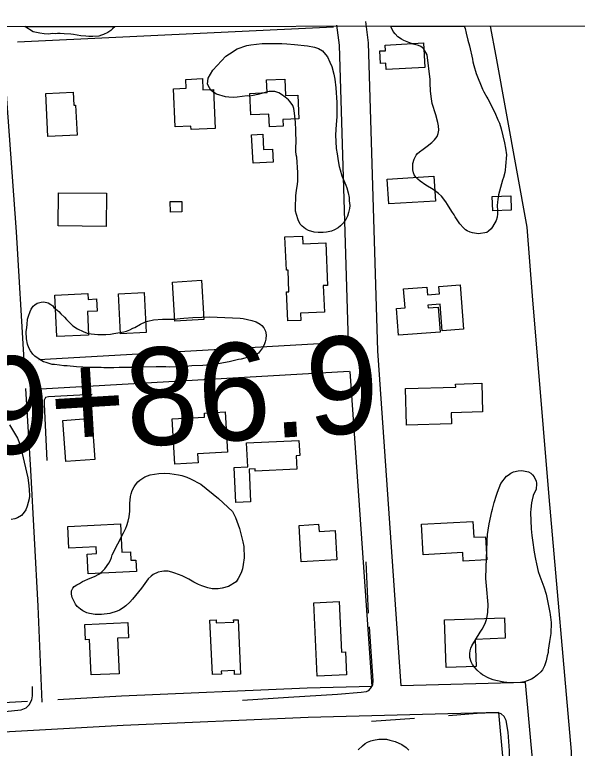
# Model space of a CAD drawing. Extents: x 3297716 to 3335574, y 688621 to 713991.
# Drawn here: x 3321388 to 3321965, y 711464 to 712216 of the extents above; entities that cross this region are included whole.
import ezdxf

# ---------------------------------------------------------------- set-up
doc = ezdxf.new("R2010")
doc.units = 0
for name, color, linetype in [('V-BLDG-OTLN', 7, 'Continuous'), ('V-GRID-FRAM', 7, 'Continuous'), ('V-LEVE-TOET', 7, 'Continuous'), ('V-ROAD-CNTR', 7, 'Continuous'), ('V-SITE-VEGE', 7, 'Continuous'), ('V-SURV-IDEN', 7, 'Continuous'), ('V-TOPO-SHOR', 7, 'Continuous')]:
    doc.layers.add(name, color=color, linetype=linetype)

msp = doc.modelspace()

# ---------------------------------------------------------------- linework, layer by layer
at = {"layer": 'V-BLDG-OTLN'}
for points in [[(3321808.59, 712162.12), (3321769.11, 712160.01), (3321768.77, 712166.46), (3321763.14, 712166.16), (3321762.45, 712179.03), (3321768.41, 712179.35), (3321768.1, 712185.17), (3321807.25, 712187.27)], [(3321552.47, 712101.35), (3321550.87, 712140.29), (3321563.62, 712140.82), (3321563.24, 712149.96), (3321580.44, 712150.67), (3321580.91, 712139.11), (3321591.73, 712139.56), (3321593.39, 712099.41), (3321568.7, 712098.39), (3321568.55, 712102.02)], [(3321648.59, 712114.35), (3321630.17, 712113.51), (3321629.16, 712135.51), (3321646.8, 712136.32), (3321646.21, 712149.28), (3321665.05, 712150.14), (3321665.82, 712133.21), (3321678.23, 712133.79), (3321679.34, 712109.47), (3321663.06, 712108.72), (3321663.37, 712101.92), (3321649.19, 712101.27)], [(3321451.8, 712092.74), (3321421.81, 712091.3), (3321419.7, 712135.32), (3321447.71, 712136.66), (3321448.34, 712123.48), (3321450.33, 712123.58)], [(3321632.42, 712064.04), (3321630.93, 712092.99), (3321642.33, 712093.57), (3321643.13, 712077.82), (3321652.24, 712078.28), (3321652.92, 712065.09)], [(3321819.45, 712025.12), (3321771.54, 712022.29), (3321770.03, 712047.7), (3321817.95, 712050.53)], [(3321482.01, 712033.23), (3321481.71, 711999.1), (3321432.48, 711999.54), (3321432.78, 712033.67)], [(3321896.88, 712030.45), (3321897.34, 712015.73), (3321878.35, 712015.12), (3321877.89, 712029.85)], [(3321547.39, 712024.49), (3321559.13, 712024.68), (3321559.3, 712013.95), (3321547.56, 712013.76)], [(3321706.92, 711982.3), (3321708.86, 711938.62), (3321704.46, 711938.43), (3321705.68, 711911.05), (3321680.97, 711909.95), (3321681.29, 711902.61), (3321668.14, 711902.03), (3321666.81, 711931.86), (3321669.23, 711931.97), (3321668.24, 711954.26), (3321666.52, 711954.18), (3321665, 711988.37), (3321683.1, 711989.17), (3321683.46, 711981.25)], [(3321579.32, 711943.76), (3321581.94, 711903.73), (3321552.19, 711901.79), (3321549.58, 711941.81)], [(3321844.93, 711939.01), (3321848.38, 711893.7), (3321826.45, 711892.03), (3321824.37, 711919.36), (3321811.77, 711918.4), (3321811.98, 711915.57), (3321822.3, 711916.36), (3321824.26, 711890.68), (3321781.51, 711887.42), (3321779.42, 711914.8), (3321788.32, 711915.48), (3321786.82, 711935.09), (3321810.61, 711936.9), (3321811.23, 711928.89), (3321823.62, 711929.83), (3321823.04, 711937.34)], [(3321431.01, 711886.08), (3321429.02, 711928.7), (3321462.88, 711930.28), (3321463.16, 711924.21), (3321471.73, 711924.61), (3321472.31, 711912.19), (3321462.35, 711911.73), (3321463.47, 711887.59)], [(3321496.25, 711888.74), (3321494.2, 711929.8), (3321520.79, 711931.12), (3321522.84, 711890.07)], [(3321836.13, 711796.48), (3321789.85, 711795.16), (3321788.78, 711832.67), (3321840.32, 711834.14), (3321840.23, 711837.38), (3321866.99, 711838.14), (3321867.83, 711808.84), (3321835.8, 711807.93)], [(3321549.52, 711801.54), (3321582.69, 711803.37), (3321582.46, 711807.52), (3321603.92, 711808.71), (3321606.2, 711767.52), (3321575.37, 711765.81), (3321575.89, 711756.52), (3321552.09, 711755.21)], [(3321467.08, 711802.18), (3321470.14, 711760.03), (3321440.14, 711757.86), (3321437.08, 711800)], [(3321625.77, 711776.98), (3321679.45, 711779.58), (3321680.21, 711763.91), (3321676.64, 711763.74), (3321677.31, 711750.08), (3321634.67, 711748.02), (3321634.55, 711750.49), (3321628.28, 711750.19), (3321629.91, 711716.46), (3321614.76, 711715.72), (3321613, 711751.88), (3321626.95, 711752.56)], [(3321442.2, 711691.28), (3321496.41, 711693.86), (3321497.79, 711664.86), (3321506.53, 711665.27), (3321506.95, 711656.57), (3321512.06, 711656.82), (3321512.62, 711645.1), (3321463.18, 711642.74), (3321462.22, 711662.9), (3321471.74, 711663.36), (3321471.41, 711670.35), (3321443.25, 711669.01)], [(3321681.87, 711654.99), (3321679.67, 711692.37), (3321699.64, 711693.55), (3321700.07, 711686.17), (3321716.71, 711687.15), (3321718.48, 711657.14)], [(3321805.26, 711693.49), (3321857.9, 711696.34), (3321858.78, 711680.12), (3321870.92, 711680.77), (3321872.21, 711657.08), (3321848.03, 711655.77), (3321847.56, 711664.46), (3321806.95, 711662.27)], [(3321698.23, 711537.73), (3321694.91, 711612.98), (3321720.86, 711614.12), (3321723.14, 711562.42), (3321727.29, 711562.6), (3321728.33, 711539.06)], [(3321459.75, 711590.78), (3321503.95, 711592.7), (3321504.64, 711577.03), (3321493.36, 711576.53), (3321494.94, 711540.22), (3321466.15, 711538.96), (3321464.58, 711575.24), (3321460.44, 711575.06)], [(3321617, 711595.58), (3321619.52, 711539.8), (3321613.34, 711539.52), (3321613.16, 711543.5), (3321599.71, 711542.89), (3321599.85, 711539.78), (3321590.66, 711539.36), (3321588.14, 711595.23), (3321594.36, 711595.51), (3321594.51, 711592.24), (3321612.53, 711593.06), (3321612.42, 711595.37)], [(3321830.42, 711546.46), (3321828.68, 711595.38), (3321890.33, 711597.57), (3321891.07, 711576.51), (3321860.4, 711575.42), (3321861.39, 711547.57)]]:
    msp.add_lwpolyline(points, close=True, dxfattribs=at)
at = {"layer": 'V-GRID-FRAM'}
msp.add_lwpolyline([(3301838.48, 712184.22), (3333346.19, 712216.3), (3333372.64, 694031.53), (3301849.06, 693999.43), (3301838.48, 712184.22)], dxfattribs=at)
at = {"layer": 'V-LEVE-TOET'}
msp.add_lwpolyline([(3322018.75, 710120.99), (3322017.11, 710139.56), (3322019.86, 710157.32), (3322023.4, 710174.89), (3322027.98, 710190.84), (3322033.99, 710207.05), (3322036.58, 710224.66), (3322036.04, 710236.16), (3322023.44, 710391.28), (3322010.09, 710623.54), (3321976.79, 711142.09), (3321968.23, 711184.67), (3321964.85, 711202.52), (3321959.29, 711460.32), (3321936.14, 711721.54), (3321919.03, 711928), (3321913.61, 711998.4), (3321881.83, 712173.64), (3321876.05, 712204.62)], dxfattribs=at)
at = {"layer": 'V-ROAD-CNTR'}
for points in [[(3321714.87, 712203.36), (3321390.53, 712188.22)], [(3321730.18, 711880.31), (3321721.01, 712185.06), (3321718.49, 712205.51)], [(3321784.5, 711527.85), (3321760.46, 711871.56), (3321750.96, 712187.35), (3321748.27, 712209.18)], [(3321397.37, 711861.61), (3321389.72, 711993.51), (3321376.57, 712172.22), (3321375.71, 712187.52)], [(3321472.96, 712192.08), (3321472.96, 712192.08)], [(3321730.18, 711880.31), (3321412.51, 711862.2)], [(3321731.08, 711850.31), (3321414.47, 711832.26)], [(3321754.48, 711527.07), (3321731.87, 711850.36)], [(3321415.94, 711510.97), (3321411.82, 711609.63), (3321404.29, 711748.96), (3321399.08, 711832.74)], [(3321754.48, 711527.07), (3321687.98, 711525.33), (3321497.45, 711517.16), (3321431.86, 711513.47)], [(3322005.03, 710252.58), (3321988.8, 710448.52), (3321987.02, 710552.46), (3321967.93, 710803.96), (3321961.25, 710892.18), (3321944.29, 711176.62), (3321912.08, 711531.19), (3321784.5, 711527.85)], [(3321401.02, 711511.73), (3321245.66, 711502.99), (3321148.07, 711496.71), (3321098.11, 711495.85), (3320964.97, 711492.11), (3320679.58, 711472.85), (3320665.92, 711471.69)], [(3321909.86, 711224.02), (3321884.74, 711500.46), (3321689.02, 711495.35), (3321498.93, 711487.2), (3321247.47, 711473.04), (3321149.29, 711466.72), (3321098.79, 711465.86), (3320966.4, 711462.13), (3320681.86, 711442.94), (3320668.08, 711441.77)]]:
    msp.add_lwpolyline(points, dxfattribs=at)
at = {"layer": 'V-SITE-VEGE'}
for p, q in [((3321398.01, 712204.13), (3321490.93, 712204.23)), ((3321406.88, 712198.83), (3321398.01, 712204.13)), ((3321490.64, 712203.88), (3321488.17, 712201.6)), ((3321490.93, 712204.23), (3321490.64, 712203.88)), ((3321774.09, 712204.52), (3321849.16, 712204.59)), ((3321774.27, 712203.49), (3321774.09, 712204.52)), ((3321776.24, 712198.96), (3321774.27, 712203.49)), ((3321849.16, 712204.59), (3321850.03, 712202.22)), ((3321413.57, 712197.38), (3321406.88, 712198.83)), ((3321418.11, 712196.61), (3321413.57, 712197.38)), ((3321422.07, 712196.45), (3321418.11, 712196.61)), ((3321424.66, 712196.55), (3321422.07, 712196.45)), ((3321426.65, 712196.86), (3321424.66, 712196.55)), ((3321429.63, 712196.75), (3321426.65, 712196.86)), ((3321431.82, 712197.06), (3321429.63, 712196.75)), ((3321434.4, 712196.96), (3321431.82, 712197.06)), ((3321438.36, 712196.8), (3321434.4, 712196.96)), ((3321445.28, 712196.14), (3321438.36, 712196.8)), ((3321448.05, 712195.83), (3321445.28, 712196.14)), ((3321455.74, 712194.53), (3321448.05, 712195.83)), ((3321476.8, 712195.3), (3321474.19, 712194.41)), ((3321478.81, 712195.82), (3321476.8, 712195.3)), ((3321483.26, 712198.02), (3321478.81, 712195.82)), ((3321486.32, 712200.08), (3321483.26, 712198.02)), ((3321488.17, 712201.6), (3321486.32, 712200.08)), ((3321778.15, 712196.58), (3321776.24, 712198.96)), ((3321781.11, 712193.54), (3321778.15, 712196.58)), ((3321850.03, 712202.22), (3321851.23, 712197.4)), ((3321851.23, 712197.4), (3321852.64, 712190.12)), ((3321460.88, 712194.14), (3321455.74, 712194.53)), ((3321463.85, 712194.02), (3321460.88, 712194.14)), ((3321467.83, 712194.06), (3321463.85, 712194.02)), ((3321474.19, 712194.41), (3321467.83, 712194.06)), ((3321784.71, 712191.25), (3321781.11, 712193.54)), ((3321787.27, 712189.91), (3321784.71, 712191.25)), ((3321792.11, 712187.72), (3321787.27, 712189.91)), ((3321796.66, 712186.16), (3321792.11, 712187.72)), ((3321852.64, 712190.12), (3321854.4, 712184.21)), ((3321801.98, 712184.72), (3321796.66, 712186.16)), ((3321804.56, 712183.7), (3321801.98, 712184.72)), ((3321807.25, 712181.75), (3321804.56, 712183.7)), ((3321811.14, 712174.98), (3321807.25, 712181.75)), ((3321854.4, 712184.21), (3321857.71, 712170.54)), ((3321814.14, 712149.64), (3321811.14, 712174.98)), ((3321857.71, 712170.54), (3321858.07, 712167.92)), ((3321858.07, 712167.92), (3321859, 712164.19)), ((3321859, 712164.19), (3321861.29, 712155.95)), ((3321814.16, 712146.26), (3321814.14, 712149.64)), ((3321861.29, 712155.95), (3321867.74, 712140.01)), ((3321814.6, 712137.79), (3321814.16, 712146.26)), ((3321815.37, 712130.07), (3321814.6, 712137.79)), ((3321867.74, 712140.01), (3321869.17, 712137.18)), ((3321869.17, 712137.18), (3321872.34, 712131.68)), ((3321816.25, 712125.11), (3321815.37, 712130.07)), ((3321872.34, 712131.68), (3321873.18, 712129.8)), ((3321873.18, 712129.8), (3321880.48, 712115.98)), ((3321819.79, 712113.44), (3321816.25, 712125.11)), ((3321821.95, 712105.66), (3321819.79, 712113.44)), ((3321880.48, 712115.98), (3321883.57, 712108.32)), ((3321822.73, 712102.1), (3321821.95, 712105.66)), ((3321883.57, 712108.32), (3321885.13, 712104.88)), ((3321885.13, 712104.88), (3321886.9, 712099.12)), ((3321822.42, 712094.27), (3321822.88, 712097.79)), ((3321822.88, 712097.79), (3321822.73, 712102.1)), ((3321886.9, 712099.12), (3321890.33, 712084.68)), ((3321818.48, 712087.81), (3321821.24, 712091.39)), ((3321821.24, 712091.39), (3321822.42, 712094.27)), ((3321811.16, 712081.48), (3321815.77, 712085.3)), ((3321815.77, 712085.3), (3321818.48, 712087.81)), ((3321890.33, 712084.68), (3321891.35, 712079.41)), ((3321801.17, 712073.88), (3321803.09, 712075.65)), ((3321803.09, 712075.65), (3321806.88, 712078.27)), ((3321806.88, 712078.27), (3321811.16, 712081.48)), ((3321891.35, 712079.41), (3321892.47, 712072.45)), ((3321796.31, 712063.61), (3321797.56, 712068.02)), ((3321797.56, 712068.02), (3321799.73, 712072.24)), ((3321799.73, 712072.24), (3321801.17, 712073.88)), ((3321892.47, 712072.45), (3321891.55, 712060.8)), ((3321796.2, 712060.69), (3321796.31, 712063.61)), ((3321796.21, 712057), (3321796.2, 712060.69)), ((3321891.55, 712060.8), (3321891.08, 712056.67)), ((3321797.01, 712053.89), (3321796.21, 712057)), ((3321797.86, 712052.02), (3321797.01, 712053.89)), ((3321799.9, 712049.17), (3321797.86, 712052.02)), ((3321890.69, 712054.53), (3321889.25, 712049.36)), ((3321891.08, 712056.67), (3321890.69, 712054.53)), ((3321801.37, 712047.57), (3321799.9, 712049.17)), ((3321803.74, 712045.33), (3321801.37, 712047.57)), ((3321809.74, 712041.4), (3321803.74, 712045.33)), ((3321888.22, 712046.47), (3321884.25, 712031.41)), ((3321889.25, 712049.36), (3321888.22, 712046.47)), ((3321817.26, 712036.95), (3321809.74, 712041.4)), ((3321822.79, 712032.74), (3321817.26, 712036.95)), ((3321825.6, 712030.02), (3321822.79, 712032.74)), ((3321830.15, 712024.45), (3321825.6, 712030.02)), ((3321884.25, 712031.41), (3321883.44, 712026.52)), ((3321832.03, 712021.61), (3321830.15, 712024.45)), ((3321836.37, 712014.52), (3321832.03, 712021.61)), ((3321883.19, 712024.07), (3321883.05, 712020.69)), ((3321883.44, 712026.52), (3321883.19, 712024.07)), ((3321838.69, 712011.05), (3321836.37, 712014.52)), ((3321883.05, 712020.69), (3321883.14, 712014.99)), ((3321883.14, 712014.99), (3321883.33, 712012.06)), ((3321839.84, 712008.85), (3321838.69, 712011.05)), ((3321843.32, 712003.64), (3321839.84, 712008.85)), ((3321882.89, 712008.54), (3321881.83, 712005.05)), ((3321883.33, 712012.06), (3321882.89, 712008.54)), ((3321844.48, 712001.75), (3321843.32, 712003.64)), ((3321848.16, 711997.6), (3321844.48, 712001.75)), ((3321881.83, 712005.05), (3321878.19, 711998.58)), ((3321850.54, 711995.51), (3321848.16, 711997.6)), ((3321852.19, 711994.37), (3321850.54, 711995.51)), ((3321855.06, 711993.18), (3321852.19, 711994.37)), ((3321857.49, 711992.32), (3321855.06, 711993.18)), ((3321863.75, 711991.3), (3321857.49, 711992.32)), ((3321872.12, 711992.97), (3321863.75, 711991.3)), ((3321874.02, 711994.28), (3321872.12, 711992.97)), ((3321876.57, 711996.49), (3321874.02, 711994.28)), ((3321878.19, 711998.58), (3321876.57, 711996.49))]:
    msp.add_line(p, q, dxfattribs=at)
for points in [[(3321677.31, 712069.94), (3321676.62, 712072.55), (3321676.16, 712076.14), (3321676.69, 712089.61), (3321676.42, 712092.8), (3321676.42, 712097.96), (3321675.94, 712105.92), (3321674.92, 712115.09), (3321674.12, 712120.08), (3321673.04, 712123.1), (3321670.61, 712126.77), (3321668.7, 712128.82), (3321665.25, 712131.74), (3321661.58, 712134.46), (3321658.86, 712135.96), (3321654.55, 712137.32), (3321649, 712137.54), (3321646, 712136.86), (3321637.37, 712134.42), (3321632.56, 712133.22), (3321628.57, 712132.78), (3321626.2, 712133.07), (3321616.02, 712131.69), (3321612.64, 712131.42), (3321607.48, 712131.62), (3321603.93, 712131.96), (3321594.71, 712134.9), (3321591.03, 712137.23), (3321589.11, 712138.89), (3321587.62, 712141.33), (3321585.78, 712144.98), (3321586.22, 712151.11), (3321591.1, 712159.26), (3321604.57, 712173.61), (3321608.04, 712176.06), (3321616.18, 712181.3), (3321626.04, 712184.68), (3321630.24, 712185.51), (3321641.79, 712186.64), (3321648.94, 712186.76), (3321661.84, 712186.65), (3321667.19, 712186.44), (3321674.91, 712185.74), (3321688.15, 712184.23), (3321695.44, 712182.95), (3321699.55, 712181.6), (3321703.62, 712179.06), (3321706.85, 712175.36), (3321708.74, 712172.91), (3321711.31, 712167.64), (3321713.11, 712163.01), (3321715.2, 712155.39), (3321716.18, 712149.99), (3321717.43, 712141.4), (3321718.41, 712126.08), (3321718.45, 712116.95), (3321718.24, 712111.6), (3321717.54, 712103.69), (3321717.12, 712092.99), (3321717.76, 712079.07), (3321718.74, 712073.67), (3321719.65, 712066.49), (3321720.8, 712060.49), (3321721.67, 712057.28), (3321723.61, 712051.06), (3321727.6, 712041.37), (3321728.49, 712038.76), (3321730.07, 712033.53), (3321731.07, 712028.73), (3321731.14, 712025.35), (3321731.54, 712020.38), (3321731.22, 712017.41), (3321730.27, 712013.48), (3321729.14, 712009.75), (3321726.76, 712004.88), (3321724.25, 712001.61), (3321722.19, 711999.51), (3321719.73, 711997.62), (3321715.87, 711995.39), (3321712.85, 711994.32), (3321707.84, 711993.12), (3321704.45, 711992.66), (3321699.29, 711992.66), (3321694.94, 711993.23), (3321689.26, 711995.04), (3321686.14, 711996.55), (3321682.68, 711999.27), (3321680.77, 712001.33), (3321678.57, 712005.78), (3321676.79, 712011.21), (3321675.94, 712014.62), (3321675.87, 712017.99), (3321676.36, 712030.48), (3321676.98, 712036.21), (3321677.81, 712042.13), (3321678.15, 712045.69), (3321678.49, 712054.41)], [(3321546.74, 711854.82), (3321542.78, 711854.97), (3321533.05, 711854.96), (3321518.16, 711854.75), (3321507.62, 711854.37), (3321494.92, 711854.27), (3321489.55, 711854.08), (3321479.23, 711854.09), (3321476.65, 711854.19), (3321464.55, 711854.27), (3321457.82, 711854.73), (3321451.08, 711854.99), (3321441.6, 711855.96), (3321438.03, 711856.1), (3321433.68, 711856.67), (3321428.75, 711857.46), (3321426.38, 711857.55), (3321419.9, 711859.39), (3321417.35, 711860.29), (3321413.86, 711862.21), (3321408.45, 711865.99), (3321406.34, 711867.86), (3321403.9, 711871.53), (3321402.42, 711874.37), (3321400.8, 711878.4), (3321400.01, 711883.59), (3321399.69, 711890.75), (3321400.07, 711895.3), (3321400.59, 711898.45), (3321401, 711903.8), (3321401.91, 711906.94), (3321403.49, 711911.64), (3321404.58, 711914.18), (3321406.69, 711917.27), (3321408.33, 711918.59), (3321410.97, 711920.28), (3321414.78, 711921.32), (3321417.77, 711921.6), (3321422.1, 711920.64), (3321425.01, 711918.93), (3321426.74, 711917.48), (3321428.06, 711915.84), (3321433.07, 711911.87), (3321435.16, 711909.41), (3321438.79, 711905.89), (3321441.07, 711903.42), (3321447.57, 711897.01), (3321452.21, 711893.85), (3321457.87, 711891.25), (3321462.17, 711889.69), (3321466.3, 711888.73), (3321473.02, 711888.07), (3321481.16, 711888.15), (3321486.14, 711888.55), (3321489.54, 711889.21), (3321495.73, 711890.16), (3321499.93, 711890.99), (3321502.34, 711891.69), (3321505.97, 711893.13), (3321509, 711894.6), (3321511.02, 711895.32), (3321516.71, 711898.67), (3321521.97, 711901.24), (3321524.38, 711901.94), (3321530.18, 711903.3), (3321539.34, 711903.93), (3321541.92, 711903.83), (3321551.45, 711904.05), (3321557.63, 711904.6), (3321561.42, 711905.05), (3321570.57, 711905.69), (3321579.72, 711906.12), (3321587.66, 711906.2), (3321619.17, 711904.97), (3321622.13, 711904.65), (3321631.19, 711902.71), (3321635.49, 711901.15), (3321639.77, 711898.8), (3321641.51, 711897.54), (3321643.39, 711895.09), (3321645.04, 711891.65), (3321645.89, 711887.84), (3321645.52, 711883.49), (3321644.81, 711880.54), (3321643.69, 711877.41), (3321642.19, 711874.49), (3321638, 711868.9), (3321634.75, 711867.05), (3321630.12, 711865.44), (3321620.1, 711862.85), (3321617.3, 711862.37), (3321607.69, 711860.17), (3321601.89, 711859.2), (3321598.48, 711858.34), (3321596.29, 711858.23), (3321588.31, 711856.96), (3321580.94, 711856.25), (3321569.61, 711855.9), (3321566.62, 711855.62)], [(3321499.33, 711684.74), (3321501.78, 711689.5), (3321502.86, 711692.37), (3321504.32, 711696.52), (3321505.31, 711701.17), (3321505.86, 711706.97), (3321505.98, 711710.04), (3321506, 711714.73), (3321506.77, 711721.98), (3321507.36, 711724.55), (3321508.47, 711728.22), (3321510.23, 711731.88), (3321511.61, 711734.09), (3321514.15, 711736.9), (3321516.16, 711738.6), (3321519.32, 711740.9), (3321521.48, 711742.28), (3321523.95, 711743.31), (3321526.9, 711744.33), (3321535.68, 711745.44), (3321541.36, 711745.86), (3321546.85, 711745.65), (3321555.85, 711744.16), (3321559.21, 711743.38), (3321564.49, 711741.72), (3321568.3, 711739.95), (3321578.61, 711734.7), (3321596.8, 711720.07), (3321611.16, 711706.73), (3321614.47, 711700.29), (3321618.41, 711689.3), (3321621.91, 711675.41), (3321622.85, 711670.68), (3321623.21, 711659.02), (3321622.29, 711652.26), (3321621.47, 711647.92), (3321620.02, 711643.77), (3321617.19, 711637.74), (3321615.12, 711634.42), (3321607.17, 711629.72), (3321600.64, 711628.03), (3321596.4, 711627.23), (3321590.25, 711627.31), (3321586.08, 711628.12), (3321579.86, 711630.3), (3321576.52, 711631.73), (3321571.6, 711634.19), (3321566.38, 711637.3), (3321559.71, 711640.48), (3321552.22, 711643.36), (3321549.18, 711644.29), (3321545.34, 711645.25), (3321540.82, 711645.42), (3321538.7, 711645.18), (3321535.11, 711644.35), (3321529.83, 711641.81), (3321527.67, 711640.27), (3321524.65, 711637.48), (3321517.81, 711628.05), (3321508.62, 711616.59), (3321506.08, 711613.62), (3321501.89, 711609.9), (3321499.22, 711607.91), (3321495.41, 711605.47), (3321492.93, 711604.27), (3321485.56, 711601.97), (3321476.95, 711600.85), (3321474.2, 711600.8), (3321470.48, 711600.94), (3321464.69, 711601.82), (3321461.81, 711602.74), (3321457.68, 711604.52), (3321455.15, 711606.24), (3321451.72, 711609.28), (3321450.19, 711611.61), (3321448.08, 711615.57), (3321446.9, 711618.37), (3321445.9, 711621.81), (3321446.04, 711625.36), (3321447.28, 711628.06), (3321448.63, 711629.62), (3321451.45, 711631.45), (3321454.42, 711632.8), (3321457.24, 711634.63), (3321465.31, 711638.19), (3321469.58, 711639.8), (3321474.04, 711642.22), (3321476.87, 711644.37), (3321480.4, 711647.79), (3321484.35, 711653.46), (3321485.94, 711656.8), (3321487.01, 711659.51), (3321487.76, 711662.06)], [(3321919.7, 711723.03), (3321918.91, 711718.45), (3321918.17, 711715.4), (3321917.47, 711709.13), (3321917.17, 711705.6), (3321917.75, 711688.97), (3321918.4, 711681.87), (3321918.98, 711677.08), (3321920.81, 711665.01), (3321922.06, 711657.73), (3321923.1, 711652.77), (3321924.95, 711645.17), (3321926.6, 711640.18), (3321930.63, 711629.26), (3321933.1, 711621.62), (3321936.98, 711602.86), (3321937.36, 711600.85), (3321937.7, 711597.76), (3321938.09, 711595.75), (3321938.27, 711592.51), (3321938.3, 711589.43), (3321938.11, 711584.67), (3321937.83, 711581.3), (3321937.22, 711577.48), (3321936.74, 711573.19), (3321935.31, 711564.18), (3321935.22, 711561.87), (3321934.33, 711558.68), (3321933.04, 711553.35), (3321931.45, 711548.18), (3321929.3, 711544.27), (3321927.52, 711542.03), (3321924.33, 711539.08), (3321920.68, 711536.3), (3321918.01, 711534.71), (3321913.63, 711532.89), (3321910.98, 711531.91), (3321906.8, 711531.31), (3321899.72, 711530.97), (3321892.81, 711531.24), (3321889.59, 711531.52), (3321881.65, 711533.06), (3321878.76, 711533.94), (3321874.37, 711535.65), (3321867.9, 711539.14), (3321866.25, 711540.28), (3321862.23, 711543.82), (3321859.88, 711546.53), (3321857.54, 711549.54), (3321856.11, 711552.36), (3321854.74, 711556.72), (3321854.91, 711560.87), (3321855.33, 711563.78), (3321855.9, 711566.52), (3321856.9, 711568.63), (3321861.53, 711576.76), (3321864.46, 711581.1), (3321865.46, 711582.91), (3321867.42, 711585.91), (3321870.42, 711591.63), (3321871.96, 711595.73), (3321872.69, 711598.77), (3321873.33, 711603.36), (3321873.49, 711611.2), (3321873.02, 711618.75), (3321872.56, 711622.92), (3321871.3, 711637.73), (3321871.44, 711649.26), (3321872.5, 711676.29), (3321873.08, 711683.03), (3321873.56, 711687.47), (3321874.58, 711693.89), (3321877.38, 711706.54), (3321878.25, 711709.12), (3321879.9, 711715.83), (3321882.04, 711723.28), (3321883.08, 711726.47), (3321886.81, 711735.24), (3321892.48, 711742.71), (3321894.08, 711744.03), (3321896.76, 711745.92), (3321899.74, 711747.34), (3321904.55, 711748.39), (3321908.1, 711748.71), (3321915.12, 711747.36), (3321917.52, 711745.88), (3321919.3, 711744.12), (3321920.76, 711742.21), (3321922.74, 711737.83), (3321923.12, 711735.66), (3321923.18, 711733.35), (3321922.94, 711731.21), (3321922.88, 711729.52)]]:
    msp.add_lwpolyline(points, close=True, dxfattribs=at)
for points in [[(3321382.58, 711795.49), (3321390.51, 711781.98), (3321391.87, 711778.44), (3321395.16, 711767.36), (3321401.1, 711740.99), (3321402.29, 711733.22), (3321402.62, 711728.98), (3321402.88, 711722.74), (3321402.75, 711719.51), (3321400.72, 711712.12), (3321399.07, 711708.2), (3321397.48, 711705.78), (3321394.87, 711702.64), (3321390.54, 711700.07), (3321387.75, 711698.94), (3321384.24, 711698.33)], [(3321740.39, 711461.94), (3321744.52, 711466.22), (3321747.46, 711468.49), (3321749.74, 711469.83), (3321753.28, 711471.27), (3321756.01, 711471.96), (3321761.28, 711472.86), (3321764.46, 711473.06), (3321769.37, 711472.86), (3321772.83, 711472.09), (3321778.32, 711470.61), (3321785.02, 711467.65), (3321789.34, 711464.47), (3321792.08, 711461.66)]]:
    msp.add_lwpolyline(points, dxfattribs=at)
at = {"layer": 'V-TOPO-SHOR'}
for p, q in [((3321750.88, 711602.15), (3321748.51, 711654.8)), ((3321797.98, 711494.28), (3321753.85, 711491.31))]:
    msp.add_line(p, q, dxfattribs=at)
for points in [[(3321467.33, 711826.47), (3321422.37, 711824.2), (3321419.37, 711823.4), (3321417.86, 711820.85), (3321417.91, 711816.68), (3321420.73, 711758.91)], [(3321751.69, 711588.37), (3321755.41, 711532.97), (3321754.89, 711528.85), (3321752.55, 711525.01), (3321750.49, 711522.68), (3321748.48, 711521.6), (3321743.29, 711520.78), (3321719.11, 711518.75), (3321668.77, 711515.92), (3321621.63, 711512.74)], [(3321360.69, 711499.85), (3321394.38, 711503.2), (3321399.55, 711505.18), (3321402.64, 711508.38), (3321405.31, 711513.44), (3321406.11, 711517.5), (3321405.92, 711527.05)], [(3321879, 711499.95), (3321862.48, 711499.28), (3321832.91, 711497.06)], [(3321895.99, 711432.64), (3321895.67, 711461), (3321894.31, 711480.13), (3321892.23, 711492.15), (3321890.2, 711496.16), (3321887.11, 711499.12), (3321883.51, 711500.13), (3321879, 711499.95)]]:
    msp.add_lwpolyline(points, dxfattribs=at)

# ---------------------------------------------------------------- texts
at = {"layer": 'V-SURV-IDEN'}
msp.add_text('3759+86.9', height=100, rotation=3.45028, dxfattribs=at).set_placement((3321129.31, 711750.26))

doc.saveas('drawing.dxf')
